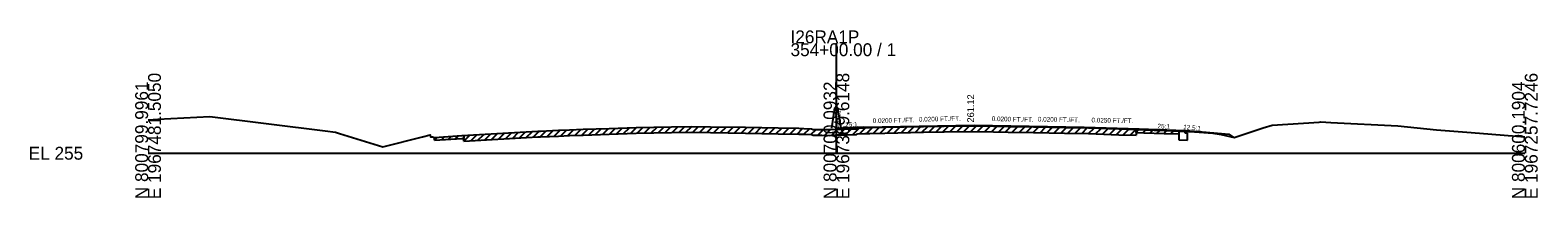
# Model space of a CAD drawing. Extents: x -26 to 304, y -10 to 7527.
# Drawn here: x -25.7 to 302.8, y 1990.3 to 2026.8 of the extents above; entities that cross this region are included whole.
import ezdxf

# ---------------------------------------------------------------- set-up
doc = ezdxf.new("R2010")
doc.units = 0
for name, color, linetype in [('RD_GPK_XS_Cell', 7, 'Continuous'), ('RD_XS_Base', 7, 'Continuous'), ('RD_XS_Box', 7, 'Continuous'), ('RD_XS_EarthShd', 7, 'Continuous'), ('RD_XS_ExGround', 7, 'Continuous'), ('RD_XS_ExPaveRet', 7, 'Continuous'), ('RD_XS_Misc_Line', 7, 'Continuous'), ('RD_XS_Pave', 7, 'Continuous'), ('RD_XS_PaveShd', 7, 'Continuous'), ('RD_XS_TX_Elev_EX', 7, 'Continuous'), ('RD_XS_TX_Elev_PR', 7, 'Continuous'), ('RD_XS_TX_Misc', 7, 'Continuous'), ('RD_XS_TX_MkPT', 7, 'Continuous'), ('RD_XS_TX_Profile', 7, 'Continuous'), ('RD_XS_TX_Station', 7, 'Continuous')]:
    doc.layers.add(name, color=color, linetype=linetype)

msp = doc.modelspace()

# ---------------------------------------------------------------- linework, layer by layer
at = {"layer": 'RD_GPK_XS_Cell'}
for p, q in [((150, 2000), (150, 2023.92)), ((0, 2000), (150, 2000)), ((150, 2000), (300, 2000))]:
    msp.add_line(p, q, dxfattribs=at)
at = {"layer": 'RD_XS_Base'}
for p, q in [((150, 2005.21), (150, 2005.4)), ((226, 2004.38), (226, 2004.94)), ((226.5, 2004.36), (226, 2004.38)), ((226.5, 2002.88), (226.5, 2004.36)), ((224.63, 2002.95), (226.5, 2002.88))]:
    msp.add_line(p, q, dxfattribs=at)
at = {"layer": 'RD_XS_Box'}
for p in [(228, 2004.78), (236.67, 2003.44)]:
    msp.add_line(p, (235.55, 2004.17), dxfattribs=at)
at = {"layer": 'RD_XS_EarthShd'}
for p, q in [((149, 2005.42), (149.67, 2009.9)), ((150, 2009.9), (149.67, 2009.9)), ((150, 2009.9), (150.33, 2009.9)), ((151, 2005.42), (150.33, 2009.9)), ((226, 2004.94), (228, 2004.78))]:
    msp.add_line(p, q, dxfattribs=at)
at = {"layer": 'RD_XS_ExGround'}
msp.add_lwpolyline([(0, 2007.28), (2.14, 2007.39), (13.46, 2007.97), (38.62, 2004.84), (40.81, 2004.56), (41.7, 2004.32), (51.18, 2001.43), (59.8, 2003.58), (61.45, 2004.04), (61.55, 2003.59), (61.96, 2003.54), (62.4, 2003.46), (68.37, 2003.83), (84.91, 2004.79), (85.51, 2004.82), (89.47, 2005), (91.86, 2005.1), (94.79, 2005.21), (100.47, 2005.4), (106.35, 2005.61), (114.04, 2005.75), (118.47, 2005.84), (122.55, 2005.78), (130.22, 2005.65), (137.33, 2005.5), (141.8, 2005.42), (142.93, 2005.38), (144.57, 2005.33), (144.9, 2005.2), (146.8, 2005.16), (148.41, 2005.14), (150.23, 2005.22), (151.02, 2005.26), (152.36, 2005.28), (154.38, 2005.31), (154.58, 2005.45), (156.22, 2005.52), (157.25, 2005.57), (160.58, 2005.64), (168.95, 2005.83), (173.46, 2005.88), (181.01, 2005.95), (187.41, 2005.83), (192.97, 2005.74), (199.71, 2005.6), (204.91, 2005.51), (211.55, 2005.28), (216.98, 2005.1), (221.38, 2004.94), (224.63, 2004.82), (228.01, 2004.63), (232, 2004.4), (233.8, 2004.06), (236.67, 2003.44), (243.02, 2005.53), (244.95, 2006.09), (255.17, 2006.76), (255.52, 2006.81), (257.73, 2006.7), (272.35, 2005.99), (280.74, 2005.11), (288.32, 2004.53), (300, 2003.58)], dxfattribs=at)
at = {"layer": 'RD_XS_ExPaveRet'}
for p, q in [((94.79, 2003.96), (100.47, 2004.15)), ((100.47, 2004.15), (106.35, 2004.36)), ((106.35, 2004.36), (114.04, 2004.5)), ((114.04, 2004.5), (118.47, 2004.59)), ((118.47, 2004.59), (122.55, 2004.53)), ((122.55, 2004.53), (130.22, 2004.4)), ((130.22, 2004.4), (137.33, 2004.25)), ((137.33, 2004.25), (141.8, 2004.17)), ((141.8, 2004.17), (142.93, 2004.13)), ((142.93, 2004.13), (144.57, 2004.08)), ((144.57, 2004.08), (144.9, 2003.95)), ((152.36, 2004.03), (154.38, 2004.06)), ((154.38, 2004.06), (154.58, 2004.2)), ((154.58, 2004.2), (156.22, 2004.27)), ((156.22, 2004.27), (157.25, 2004.32)), ((157.25, 2004.32), (160.58, 2004.39)), ((160.58, 2004.39), (168.95, 2004.58)), ((168.95, 2004.58), (173.46, 2004.63)), ((173.46, 2004.63), (181.01, 2004.7)), ((181.01, 2004.7), (187.41, 2004.58)), ((187.41, 2004.58), (192.97, 2004.49)), ((192.97, 2004.49), (199.71, 2004.35)), ((199.71, 2004.35), (204.91, 2004.26)), ((204.91, 2004.26), (211.55, 2004.03)), ((215.3, 2005.15), (215.3, 2003.9)), ((215.3, 2004.53), (215.3, 2005.15)), ((215.3, 2004.53), (216.98, 2004.47)), ((216.98, 2004.47), (221.38, 2004.32)), ((221.38, 2004.32), (224.63, 2004.2)), ((224.63, 2004.82), (224.63, 2004.2)), ((62.4, 2002.83), (62.4, 2003.46)), ((62.4, 2002.83), (68.37, 2003.21)), ((68.37, 2003.21), (68.79, 2003.23)), ((68.79, 2002.61), (68.79, 2003.86)), ((68.79, 2003.86), (68.79, 2003.23)), ((68.79, 2002.61), (84.91, 2003.54)), ((84.91, 2003.54), (85.51, 2003.57)), ((85.51, 2003.57), (89.47, 2003.75)), ((89.47, 2003.75), (91.86, 2003.85)), ((91.86, 2003.85), (94.79, 2003.96)), ((144.9, 2003.95), (146.8, 2003.91)), ((146.8, 2003.91), (148.41, 2003.89)), ((148.41, 2003.89), (150.23, 2003.97)), ((150.23, 2003.97), (151.02, 2004.01)), ((151.02, 2004.01), (152.36, 2004.03)), ((211.55, 2004.03), (215.3, 2003.9))]:
    msp.add_line(p, q, dxfattribs=at)
at = {"layer": 'RD_XS_Misc_Line'}
for p, q in [((71.81, 2002.78), (73.15, 2004.11)), ((73.33, 2002.87), (74.67, 2004.2)), ((74.84, 2002.96), (76.18, 2004.29)), ((76.35, 2003.05), (77.69, 2004.37)), ((77.87, 2003.13), (79.21, 2004.46)), ((79.38, 2003.22), (80.72, 2004.55)), ((80.89, 2003.31), (82.23, 2004.64)), ((82.4, 2003.4), (83.74, 2004.73)), ((83.92, 2003.49), (85.25, 2004.81)), ((85.43, 2003.57), (86.75, 2004.88)), ((86.94, 2003.64), (88.26, 2004.94)), ((88.46, 2003.7), (89.77, 2005.01)), ((89.97, 2003.77), (91.28, 2005.07)), ((91.48, 2003.83), (92.79, 2005.13)), ((92.99, 2003.89), (94.31, 2005.19)), ((94.51, 2003.95), (95.82, 2005.24)), ((96.02, 2004), (97.33, 2005.29)), ((97.53, 2004.05), (98.84, 2005.35)), ((99.05, 2004.1), (100.35, 2005.4)), ((100.56, 2004.16), (101.87, 2005.45)), ((102.07, 2004.21), (103.38, 2005.5)), ((103.59, 2004.26), (104.89, 2005.56)), ((105.1, 2004.31), (106.4, 2005.61)), ((106.61, 2004.36), (107.9, 2005.64)), ((108.12, 2004.39), (109.41, 2005.67)), ((109.64, 2004.42), (110.92, 2005.69)), ((111.15, 2004.45), (112.44, 2005.72)), ((112.66, 2004.48), (113.95, 2005.75)), ((114.18, 2004.51), (115.46, 2005.78)), ((115.69, 2004.54), (116.97, 2005.81)), ((117.2, 2004.56), (118.49, 2005.84)), ((118.71, 2004.59), (119.96, 2005.82)), ((120.23, 2004.56), (121.47, 2005.79)), ((121.74, 2004.54), (122.98, 2005.77)), ((123.25, 2004.52), (124.49, 2005.75)), ((124.77, 2004.49), (126.01, 2005.72)), ((126.28, 2004.47), (127.52, 2005.7)), ((127.79, 2004.44), (129.03, 2005.67)), ((129.3, 2004.42), (130.54, 2005.65)), ((130.82, 2004.39), (132.05, 2005.61)), ((132.33, 2004.36), (133.56, 2005.58)), ((133.84, 2004.33), (135.08, 2005.55)), ((135.36, 2004.29), (136.59, 2005.52)), ((136.87, 2004.26), (138.1, 2005.49)), ((138.38, 2004.23), (139.62, 2005.46)), ((139.89, 2004.2), (141.13, 2005.43)), ((141.41, 2004.17), (142.63, 2005.39)), ((142.92, 2004.13), (144.14, 2005.34)), ((144.43, 2004.08), (145.55, 2005.19)), ((145.95, 2003.93), (147.18, 2005.16)), ((147.46, 2003.9), (148.72, 2005.16)), ((148.97, 2003.92), (150.29, 2005.22)), ((150.48, 2003.98), (151.78, 2005.27)), ((152, 2004.02), (153.28, 2005.29)), ((153.51, 2004.04), (154.95, 2005.47)), ((155.02, 2004.22), (156.34, 2005.53)), ((156.54, 2004.29), (157.84, 2005.58)), ((158.05, 2004.34), (159.34, 2005.61)), ((159.56, 2004.37), (160.85, 2005.65)), ((161.08, 2004.4), (162.37, 2005.68)), ((162.59, 2004.44), (163.88, 2005.71)), ((164.1, 2004.47), (165.39, 2005.75)), ((165.61, 2004.5), (166.9, 2005.78)), ((167.13, 2004.54), (168.42, 2005.82)), ((168.64, 2004.57), (169.92, 2005.84)), ((170.15, 2004.59), (171.43, 2005.86)), ((171.67, 2004.61), (172.94, 2005.88)), ((173.18, 2004.63), (174.45, 2005.89)), ((174.69, 2004.64), (175.96, 2005.91)), ((176.2, 2004.66), (177.48, 2005.92)), ((177.72, 2004.67), (178.99, 2005.93)), ((179.23, 2004.69), (180.5, 2005.95)), ((180.74, 2004.7), (181.99, 2005.93)), ((182.26, 2004.68), (183.49, 2005.91)), ((183.77, 2004.65), (185.01, 2005.88)), ((185.28, 2004.62), (186.52, 2005.85)), ((186.79, 2004.59), (188.03, 2005.82)), ((188.31, 2004.57), (189.55, 2005.8)), ((189.82, 2004.54), (191.06, 2005.77)), ((191.33, 2004.52), (192.57, 2005.75)), ((192.85, 2004.5), (194.08, 2005.72)), ((194.36, 2004.46), (195.59, 2005.69)), ((195.87, 2004.43), (197.11, 2005.66)), ((197.38, 2004.4), (198.62, 2005.63)), ((198.9, 2004.37), (200.13, 2005.6)), ((200.41, 2004.34), (201.65, 2005.57)), ((201.92, 2004.31), (203.16, 2005.54)), ((203.44, 2004.28), (204.67, 2005.51)), ((204.95, 2004.26), (206.17, 2005.46)), ((206.46, 2004.2), (207.68, 2005.41)), ((207.97, 2004.15), (209.19, 2005.36)), ((209.49, 2004.1), (210.71, 2005.31)), ((211, 2004.05), (212.22, 2005.26)), ((212.51, 2004), (213.73, 2005.21)), ((214.03, 2003.95), (215.24, 2005.16)), ((215.3, 2004.53), (215.91, 2005.13)), ((216.82, 2004.48), (217.43, 2005.08)), ((218.33, 2004.42), (218.94, 2005.03)), ((219.85, 2004.37), (220.46, 2004.97)), ((221.37, 2004.32), (221.98, 2004.92)), ((222.88, 2004.26), (223.49, 2004.86)), ((62.4, 2002.83), (63.08, 2003.5)), ((63.92, 2002.93), (64.59, 2003.59)), ((65.43, 2003.02), (66.11, 2003.69)), ((66.95, 2003.12), (67.63, 2003.78)), ((68.79, 2002.61), (70.13, 2003.93)), ((70.3, 2002.69), (71.64, 2004.02))]:
    msp.add_line(p, q, dxfattribs=at)
at = {"layer": 'RD_XS_Pave'}
for p, q in [((156, 2005.64), (180, 2006.12)), ((180, 2006.12), (204, 2005.64)), ((204, 2005.64), (216, 2005.34))]:
    msp.add_line(p, q, dxfattribs=at)
at = {"layer": 'RD_XS_PaveShd'}
for p, q in [((156, 2005.64), (150, 2005.4)), ((216, 2005.34), (226, 2004.94))]:
    msp.add_line(p, q, dxfattribs=at)
at = {"layer": 'RD_XS_TX_Elev_PR'}
for p, q in [((150, 2005.21), (150.23, 2005.22)), ((150.23, 2005.22), (151.02, 2005.26)), ((151.02, 2005.26), (152.36, 2005.28)), ((152.36, 2005.28), (154.38, 2005.31)), ((154.38, 2005.31), (154.58, 2005.45)), ((154.58, 2005.45), (156.22, 2005.52)), ((156.22, 2005.52), (157.25, 2005.57)), ((157.25, 2005.57), (160.58, 2005.64)), ((160.58, 2005.64), (168.95, 2005.83)), ((168.95, 2005.83), (173.46, 2005.88)), ((173.46, 2005.88), (181.01, 2005.95)), ((181.01, 2005.95), (187.41, 2005.83)), ((187.41, 2005.83), (192.97, 2005.74)), ((192.97, 2005.74), (199.71, 2005.6)), ((199.71, 2005.6), (204.91, 2005.51)), ((204.91, 2005.51), (211.55, 2005.28)), ((211.55, 2005.28), (215.3, 2005.15)), ((216.98, 2005.1), (215.3, 2005.15)), ((221.38, 2004.94), (216.98, 2005.1)), ((224.63, 2004.82), (221.38, 2004.94)), ((224.63, 2004.82), (224.63, 2002.95))]:
    msp.add_line(p, q, dxfattribs=at)

# ---------------------------------------------------------------- texts
at = {"layer": 'RD_GPK_XS_Cell'}
for s, p in [('354+00.00 / 1', (140, 2021.12)), ('I26RA1P', (140, 2023.92)), ('EL 255', (-26, 1998.6))]:
    msp.add_text(s, height=2.8, dxfattribs=at).set_placement(p)
for s, p in [('E 1967481.5050', (2.8, 1990)), ('E 1967369.6148', (152.8, 1990)), ('E 1967257.7246', (302.8, 1990)), ('N 800799.9961', (0, 1990)), ('N 800700.0932', (150, 1990)), ('N 800600.1904', (300, 1990))]:
    msp.add_text(s, height=2.8, rotation=90, dxfattribs=at).set_placement(p)
at = {"layer": 'RD_XS_TX_Elev_EX'}
msp.add_text('260.21', height=1, rotation=90, dxfattribs=at).set_placement((151, 2005.21))
at = {"layer": 'RD_XS_TX_Misc'}
msp.add_text('12.5:1', height=1, rotation=355.4261, dxfattribs=at).set_placement((225.54, 2005.23))
at = {"layer": 'RD_XS_TX_MkPT'}
for rotation, p in [(2.2906, (151.94, 2005.73)), (357.7094, (219.96, 2005.43))]:
    msp.add_text('25:1', height=1, rotation=rotation, dxfattribs=at).set_placement(p)
at = {"layer": 'RD_XS_TX_Profile'}
for s, rotation, p in [('0.0200 FT./FT.', 1.1458, (157.92, 2006.57)), ('0.0200 FT./FT.', 1.1458, (167.98, 2006.88)), ('0.0200 FT./FT.', 358.5679, (183.83, 2007.02)), ('0.0200 FT./FT.', 358.8542, (193.89, 2006.92)), ('0.0250 FT./FT.', 358.8542, (205.57, 2006.73))]:
    msp.add_text(s, height=1, rotation=rotation, dxfattribs=at).set_placement(p)
at = {"layer": 'RD_XS_TX_Station'}
msp.add_text(' 261.12', height=1.5, rotation=90, dxfattribs=at).set_placement((180, 2006.12))

doc.saveas('drawing.dxf')
